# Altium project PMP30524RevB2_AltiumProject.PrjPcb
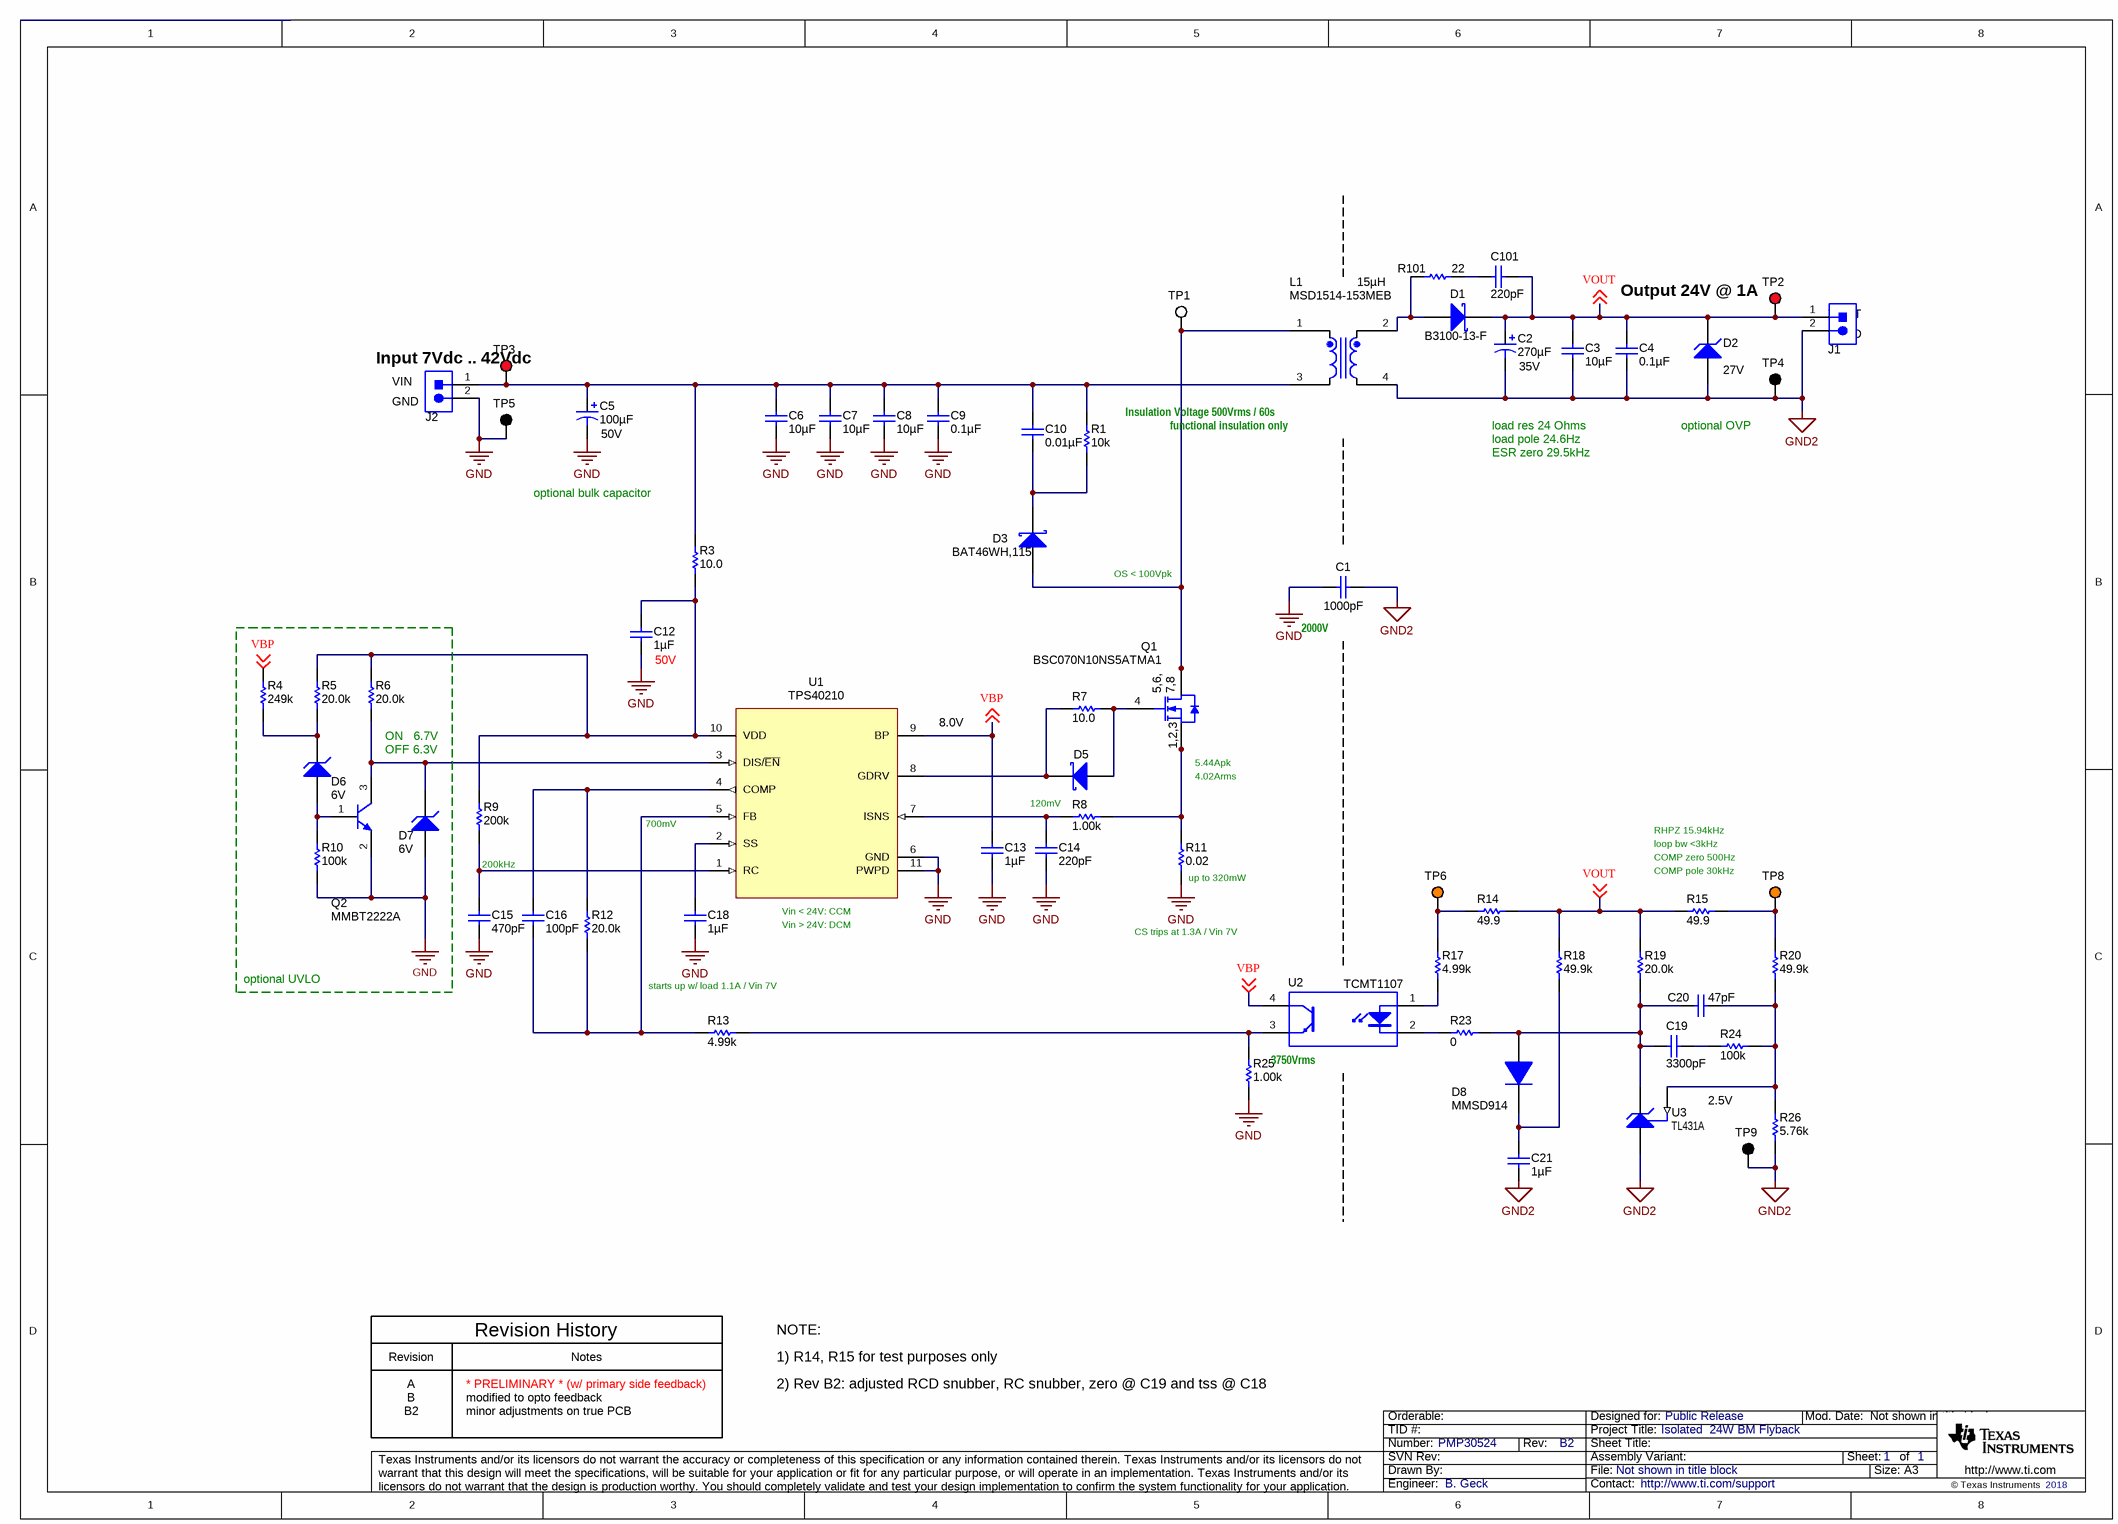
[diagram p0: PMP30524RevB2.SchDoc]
CopyrightYear: 2018; PCB_Layout: B. Geck; PCB_Rev: B; PRJ_Customer: Public Release; PRJ_Engineer: B. Geck; PRJ_Number: PMP30524; PRJ_Title: Isolated  24W BM Flyback; SCH_Rev: B2; TechSupport: http://www.ti.com/support
1 sheet, 66 parts. Net scope: global (net labels, ports and power ports of the same name join across sheets).

## Sheet PMP30524RevB2.SchDoc
size A3; Date: Not shown in title block; ApprovedBy: Not shown in title block; CheckedBy: Not shown in title block; Author: Not shown in title block; CompanyName: Not shown in title block; Engineer: Not shown in title block; Organization: Not shown in title block; Address1: Not shown in title block; Address2: Not shown in title block; Address3: Not shown in title block; Address4: Not shown in title block; DocumentNumber: 1; Revision: Use project parameter SCH_Rev; SheetNumber: 1; SheetTotal: 1; PageSetup: Record=PageOptions¦CenterHorizontal=True¦CenterVertical=True¦PrintScale=0.68¦XCorrection=1.00¦YCorrection=1.00¦PrintKind=0¦BorderSize=5000000¦LeftOffset=0¦BottomOffset=0¦Orientation=2¦PaperLength=1000¦PaperWidth=1000¦Scale=100¦PaperSource=15¦PrintQuality=600¦MediaType=1¦DitherType=10¦PrintScaleMode=1¦PaperKind=A4¦PaperIndex=9

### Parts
C1  ValueDisplayed: 1000pF  [1206_180]  (hidden comment: C1206C102KGRACAUTO)
C2  ValueDisplayed: 270µF  Value2: 35V  [SM_RADIAL_10BMM]  (hidden comment: EEHZC1V271P)
C3  ValueDisplayed: 10µF  [1210_270]  (hidden comment: GRM32ER71H106KA12L)
C4  ValueDisplayed: 0.1µF  [0603]  (hidden comment: GCM188R71H104KA57D)
C5  ValueDisplayed: 100µF  Value2: 50V  [SM_RADIAL_10BMM]  (hidden comment: EEHZC1H101P)
C6  ValueDisplayed: 10µF  [1210_270]  (hidden comment: GRM32ER71H106KA12L)
C7  ValueDisplayed: 10µF  [1210_270]  (hidden comment: GRM32ER71H106KA12L)
C8  ValueDisplayed: 10µF  [1210_270]  (hidden comment: GRM32ER71H106KA12L)
C9  ValueDisplayed: 0.1µF  [0603]  (hidden comment: GCM188R71H104KA57D)
C10  ValueDisplayed: 0.01µF  [0805_HV]  (hidden comment: GRM21BR72A103MA01L)
C12  ValueDisplayed: 1µF  Value2: 50V  [0603]  (hidden comment: UMK107AB7105KA-T)
C13  ValueDisplayed: 1µF  [0603]  (hidden comment: GRM188R71C105KA12D)
C14  ValueDisplayed: 220pF  [0603]  (hidden comment: GRM188R71H221KA01D)
C15  ValueDisplayed: 470pF  [0603]  (hidden comment: GRM1885C1H471JA01D)
C16  ValueDisplayed: 100pF  [0603]  (hidden comment: GRM1885C1H101JA01D)
C18  ValueDisplayed: 1µF  [0603]  (hidden comment: GRM188R71C105KA12D)
C19  ValueDisplayed: 3300pF  [0603]  (hidden comment: GRM188R71E332KA01D)
C20  ValueDisplayed: 47pF  [0603]  (hidden comment: GRM1885C1H470JA01D)
C21  ValueDisplayed: 1µF  [0603]  (hidden comment: GRM188R71C105KA12D)
C101  ValueDisplayed: 220pF  [0805_HV]  (hidden comment: GRM2165C2A221JA01D)
D1  B3100-13-F  [SMC]
D2  value 27V  [SOD-123]  (hidden comment: MMSZ5254B-7-F)
D3  BAT46WH,115  [SOD-123F]
D5  BAT54LP-7  [X1-DFN1006-2]  (value not drawn)
D6  value 6V  [SOD-323]  (hidden comment: MMSZ5233BS-7-F)
D7  value 6V  [SOD-323]  (hidden comment: MMSZ5233BS-7-F)
D8  MMSD914  [SOD-123]
J1  ED555/2DS  [TERM_BLK_ED555-2DS]  (value not drawn)
J2  ED555/2DS  [TERM_BLK_ED555-2DS]  (value not drawn)
L1  MSD1514-153MEB  ValueDisplayed: 15µH  [MSD1514]
Q1  BSC070N10NS5ATMA1  [PG-TDSON-8]
Q2  MMBT2222A  [SOT-23]
R1  ValueDisplayed: 10k  [1206]  (hidden comment: CRCW120610K0JNEA)
R3  ValueDisplayed: 10.0  [0603]  (hidden comment: CRCW060310R0FKEA)
R4  ValueDisplayed: 249k  [0603]  (hidden comment: CRCW0603249KFKEA)
R5  ValueDisplayed: 20.0k  [0603]  (hidden comment: CRCW060320K0FKEA)
R6  ValueDisplayed: 20.0k  [0603]  (hidden comment: CRCW060320K0FKEA)
R7  ValueDisplayed: 10.0  [0603]  (hidden comment: CRCW060310R0FKEA)
R8  ValueDisplayed: 1.00k  [0603]  (hidden comment: CRCW06031K00FKEA)
R9  ValueDisplayed: 200k  [0603]  (hidden comment: CRCW0603200KFKEA)
R10  value 100k  [0603]  (hidden comment: CRCW0603100KFKEA)
R11  ValueDisplayed: 0.02  [WSLP0805]  (hidden comment: WSLP0805R0200FEB)
R12  ValueDisplayed: 20.0k  [0603]  (hidden comment: CRCW060320K0FKEA)
R13  ValueDisplayed: 4.99k  [0603]  (hidden comment: CRCW06034K99FKEA)
R14  ValueDisplayed: 49.9  [0603]  (hidden comment: CRCW060349R9FKEA)
R15  ValueDisplayed: 49.9  [0603]  (hidden comment: CRCW060349R9FKEA)
R17  ValueDisplayed: 4.99k  [0603]  (hidden comment: CRCW06034K99FKEA)
R18  ValueDisplayed: 49.9k  [0603]  (hidden comment: CRCW060349K9FKEA)
R19  ValueDisplayed: 20.0k  [0603]  (hidden comment: CRCW060320K0FKEA)
R20  ValueDisplayed: 49.9k  [0603]  (hidden comment: CRCW060349K9FKEA)
R23  ValueDisplayed: 0  [0603]  (hidden comment: CRCW06030000Z0EA)
R24  ValueDisplayed: 100k  [0603]  (hidden comment: CRCW0603100KFKEA)
R25  ValueDisplayed: 1.00k  [0603]  (hidden comment: CRCW06031K00FKEA)
R26  ValueDisplayed: 5.76k  [0603]  (hidden comment: CRCW06035K76FKEA)
R101  ValueDisplayed: 22  [1206]  (hidden comment: CRCW120622R0JNEA)
TP1  5002  [Keystone5002]  (value not drawn)
TP2  5000  [Keystone5000]  (value not drawn)
TP3  5000  [Keystone5000]  (value not drawn)
TP4  5001  [Keystone5001]  (value not drawn)
TP5  5001  [Keystone5001]  (value not drawn)
TP6  5003  [Keystone5003]  (value not drawn)
TP8  5003  [Keystone5003]  (value not drawn)
TP9  5001  [Keystone5001]  (value not drawn)
U1  TPS40210  [DGQ0010D_N]
U2  TCMT1107  [SOP-4]
U3  TL431A  [DBZ0003A_N]

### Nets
GND: C1.2 C5.2(-) C6.2 C7.2 C8.2 C9.2 C12.2 C13.2 C14.2 C15.2 C18.2 D7.2(A) J2.2 Q2.2(E) R10.1 R11.1 R25.1 TP5.1 U1.6(GND) U1.11(PWPD)
GND2: C1.1 C2.2(-) C3.2 C4.2 C21.2 D2.2(A) J1.2 L1.4 R26.1 TP4.1 TP9.1 U3.3(ANODE)
VBP: C13.1 R4.2 U1.9(BP) U2.4(C) ; off-sheet VBP
VOUT: C2.1(+) C3.1 C4.1 C101.1 D1.1(K) D2.1(K) J1.1 R14.2 R15.1 R18.2 R19.2 TP2.1 ; off-sheet VOUT
NetC5_1: C5.1(+) C6.1 C7.1 C8.1 C9.1 C10.1 J2.1 L1.3 R1.2 R3.2 TP3.1
NetC10_2: C10.2 D3.1(K) R1.1
NetC12_1: C12.1 R3.1 R5.2 R6.2 R9.2 U1.10(VDD)
NetC14_1: C14.1 R8.1 U1.7(ISNS)
NetC15_1: C15.1 R9.1 U1.1(RC)
NetC16_1: C16.1 R12.2 U1.4(COMP)
NetC16_2: C16.2 R12.1 R13.2 U1.5(FB)
NetC18_1: C18.1 U1.2(SS)
NetC19_1: C19.1 R24.1
NetC19_2: C19.2 C20.1 D8.2(A) R19.1 R23.1 U3.1(CATHODE)
NetC20_2: C20.2 R20.1 R24.2 R26.2 U3.2(REF)
NetC21_1: C21.1 D8.1(K) R18.1
NetC101_2: C101.2 R101.2
NetD1_2: D1.2(A) L1.2 R101.1
NetD3_2: D3.2(A) L1.1 Q1.5(D) Q1.6(D) Q1.7(D) Q1.8(D) Q1.9(D) TP1.1
NetD5_1: D5.1(K) R7.2 U1.8(GDRV)
NetD5_2: D5.2(A) Q1.4(G) R7.1
NetD6_1: D6.1(K) R4.1 R5.1
NetD6_2: D6.2(A) Q2.1(B) R10.2
NetD7_1: D7.1(K) Q2.3(C) R6.1 U1.3(DIS/~{EN})
NetQ1_1: Q1.1(S) Q1.2(S) Q1.3(S) R8.2 R11.2
NetR13_1: R13.1 R25.2 U2.3(E)
NetR14_1: R14.1 R17.2 TP6.1
NetR15_2: R15.2 R20.2 TP8.1
NetR17_1: R17.1 U2.1(A)
NetR23_2: R23.2 U2.2(K)

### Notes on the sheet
- Output 24V @ 1A
- (near J1) VOUT
- (near J1) GND
- (near J2) VIN
- (near J2) GND
- Input 7Vdc .. 42Vdc
- (near L1) Insulation Voltage 500Vrms / 60s
- (near L1) functional insulation only
- load res 24 Ohms
- load pole 24.6Hz
- ESR zero 29.5kHz
- optional OVP
- optional bulk capacitor
- OS < 100Vpk
- (near C1) 2000V
- (near R6) ON   6.7V
- (near U1) 8.0V
- OFF 6.3V
- 120mV
- (near Q1) 5.44Apk
- 4.02Arms
- 200kHz
- 700mV
- (near R11) up to 320mW
- RHPZ 15.94kHz
- loop bw <3kHz
- COMP zero 500Hz
- COMP pole 30kHz
- (near U1) Vin < 24V: CCM
- (near U1) Vin > 24V: DCM
- CS trips at 1.3A / Vin 7V
- optional UVLO
- starts up w/ load 1.1A / Vin 7V
- (near U2) 3750Vrms
- 2.5V
- Revision History
- NOTE:
- Revision
- A
- B
- B2
- * PRELIMINARY * (w/ primary side feedback)
- modified to opto feedback
- minor adjustments on true PCB
- Notes
- 1) R14, R15 for test purposes only
- 2) Rev B2: adjusted RCD snubber, RC snubber, zero @ C19 and tss @ C18

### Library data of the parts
C1 = C1206C102KGRACAUTO: CAP, CERM, 1000 pF, 2000 V,+/- 10%, X7R, AEC-Q200 Grade 1, 1206; Manufacturer: Kemet; Polarized: N; CompType: Capacitor; Value: 1000pF; U/M: EA; Cap_F: 0.000000001; Tolerance_%: 10; VDC_V: 2000; Value2: 2000V; TaMin_C: -55; TaMax_C: 125; Cap_Case: 1206; SizeArea_mm2: 5.12; SizeAreaWB_mm2: 10.92; SizeX_mm: 3.2; SizeY_mm: 1.6; SizeZ_mm: 1.8; AEC Category: Q200; AEC Qualified: Y; AEC Grade: 1
C2 = EEHZC1V271P: CAP, Polymer Hybrid, 270 µF, 35 V,+/- 20%, 20 ohm, 10x10 SMD; Manufacturer: Panasonic; Polarized: Y; CompType: Capacitor; Value: 270uF; U/M: EA; Cap_F: 0.00027; Tolerance_%: 20; Value1: 20 ohm; VDC_V: 35; IRMS_A: 2; TaMin_C: -55; TaMax_C: 125; SizeAreaWB_mm2: 159.9; SizeArea_mm2: 113.3; SizeX_mm: 11; SizeY_mm: 10.3; SizeZ_mm: 10.2; AEC Category: Q200
C3 C6-C8 = GRM32ER71H106KA12L: CAP, CERM, 10 µF, 50 V,+/- 10%, X7R, 1210; Manufacturer: MuRata; Polarized: N; CompType: Capacitor; Value: 10uF; U/M: EA; Cap_F: 0.00001; Tolerance_%: 10; Value1: Unknown; VDC_V: 50; Value2: 50V; TaMin_C: -55; TaMax_C: 125; Cap_Case: 1210; SizeArea_mm2: 8; SizeAreaWB_mm2: 14.7; SizeX_mm: 3.2; SizeY_mm: 2.5; SizeZ_mm: 2.7; AEC Category: Q200; Green_Lifecycle: Active; Green_REACh: Passed
C4 C9 = GCM188R71H104KA57D: CAP, CERM, 0.1 µF, 50 V, +/- 10%, X7R, 0603; Manufacturer: MuRata; Polarized: N; CompType: Capacitor; Value: 0.1uF; U/M: EA; Cap_F: 0.0000001; Tolerance_%: 10; ESR_ohm: 0.02; Value1: 0.02 ohm; VDC_V: 50; Value2: 50V; IRMS_A: 1.84; TaMin_C: -55; TaMax_C: 125; AEC Category: Q200
C5 = EEHZC1H101P: CAP, Polymer Hybrid, 100 µF, 50 V,+/- 20%, 28 ohm, 10x10 SMD; Manufacturer: Panasonic; Polarized: Y; CompType: Capacitor; Value: 100uF; U/M: EA; Cap_F: 0.0001; Tolerance_%: 20; Value1: 28 ohm; VDC_V: 50; ESR_ohm: 28; IRMS_A: 1.6; TaMin_C: -55; TaMax_C: 125; SizeAreaWB_mm2: 159.9; SizeArea_mm2: 113.3; SizeX_mm: 11; SizeY_mm: 10.3; SizeZ_mm: 10.2; AEC Category: Q200; Green_Lifecycle: Active; Green_REACh: Passed
C10 = GRM21BR72A103MA01L: CAP, CERM, 0.01 µF, 100 V, +/- 20%, X7R, 0805; Manufacturer: MuRata; Polarized: N; CompType: Capacitor; Value: 0.01uF; U/M: EA; Cap_F: 0.00000001; Tolerance_%: 20; Value1: Unknown; VDC_V: 100; Value2: 100V; TaMin_C: -55; TaMax_C: 125; Cap_Case: 0805; SizeArea_mm2: 2.5; SizeAreaWB_mm2: 6.75; SizeX_mm: 2; SizeY_mm: 1.25; SizeZ_mm: 1.45; AEC Category: Q200
C12 = UMK107AB7105KA-T: CAP, CERM, 1 µF, 50 V,+/- 10%, X7R, 0603; Manufacturer: Taiyo Yuden; Polarized: N; CompType: Capacitor; Value: 1uF; U/M: EA; Cap_F: 0.000001; Tolerance_%: 10; VDC_V: 50; TaMin_C: -55; TaMax_C: 125; SizeArea_mm2: 1.28; SizeAreaWB_mm2: 4.68; SizeX_mm: 1.6; SizeY_mm: 0.8; SizeZ_mm: 1; AEC Category: Q200; Green_Lifecycle: Active; Green_REACh: Passed
C13 C21 = GRM188R71C105KA12D: CAP, CERM, 1 µF, 16 V, +/- 10%, X7R, 0603; Manufacturer: MuRata; Polarized: N; CompType: Capacitor; Value: 1uF; U/M: EA; Cap_F: 0.000001; Tolerance_%: 10; ESR_ohm: 0.011; Value1: 0.011 ohm; VDC_V: 16; Value2: 16V; TaMin_C: -55; TaMax_C: 125; AEC Category: Q200
C14 = GRM188R71H221KA01D: CAP, CERM, 220 pF, 50 V,+/- 10%, X7R, 0603; Manufacturer: MuRata; Polarized: N; CompType: Capacitor; Value: 220pF; U/M: EA; Cap_F: 0.00000000022; Tolerance_%: 10; Value1: Unknown; VDC_V: 50; Value2: 50V; TaMin_C: -55; TaMax_C: 125; SizeArea_mm2: 1.28; SizeAreaWB_mm2: 4.68; SizeX_mm: 1.6; SizeY_mm: 0.8; SizeZ_mm: 1; AEC Category: Q200; Green_Lifecycle: Active; Green_REACh: Passed
C15 = GRM1885C1H471JA01D: CAP, CERM, 470 pF, 50 V, +/- 5%, C0G/NP0, 0603; Manufacturer: MuRata; Polarized: N; CompType: Capacitor; Value: 470pF; U/M: EA; Cap_F: 0.00000000047; Tolerance_%: 5; Value1: Unknown; VDC_V: 50; Value2: 50V; TaMin_C: -55; TaMax_C: 125; SizeArea_mm2: 1.28; SizeAreaWB_mm2: 4.68; SizeX_mm: 1.6; SizeY_mm: 0.8; SizeZ_mm: 1; AEC Category: Q200
C16 = GRM1885C1H101JA01D: CAP, CERM, 100 pF, 50 V,+/- 5%, C0G/NP0, 0603; Manufacturer: MuRata; Polarized: N; CompType: Capacitor; Value: 100pF; U/M: EA; Cap_F: 0.0000000001; Tolerance_%: 5; VDC_V: 50; Value2: 50V; TaMin_C: -55; TaMax_C: 125; SizeArea_mm2: 1.28; SizeAreaWB_mm2: 4.68; SizeX_mm: 1.6; SizeY_mm: 0.8; SizeZ_mm: 1; AEC Category: Q200; Green_Lifecycle: Active; Green_REACh: Passed
C18 = GRM188R71C105KA12D: CAP, CERM, 1 µF, 16 V,+/- 10%, X7R, 0603; Manufacturer: MuRata; Polarized: N; CompType: Capacitor; Value: 1uF; U/M: EA; Cap_F: 0.000001; Tolerance_%: 10; ESR_ohm: 0.011; Value1: 0.011 ohm; VDC_V: 16; Value2: 16V; TaMin_C: -55; TaMax_C: 125; SizeArea_mm2: 1.28; SizeAreaWB_mm2: 4.68; SizeX_mm: 1.6; SizeY_mm: 0.8; SizeZ_mm: 1; AEC Category: Q200; Green_Lifecycle: Active; Green_REACh: Passed
C19 = GRM188R71E332KA01D: CAP, CERM, 3300 pF, 25 V,+/- 10%, X7R, 0603; Manufacturer: MuRata; Polarized: N; CompType: Capacitor; Value: 3300pF; U/M: EA; Cap_F: 0.0000000033; Tolerance_%: 10; VDC_V: 25; Value2: 25V; TaMin_C: -55; TaMax_C: 125; SizeArea_mm2: 1.28; SizeAreaWB_mm2: 4.68; SizeX_mm: 1.6; SizeY_mm: 0.8; SizeZ_mm: 1; AEC Category: Q200; Green_Lifecycle: Active; Green_REACh: Passed
C20 = GRM1885C1H470JA01D: CAP, CERM, 47 pF, 50 V,+/- 5%, C0G/NP0, 0603; Manufacturer: MuRata; Polarized: N; CompType: Capacitor; Value: 47pF; U/M: EA; Cap_F: 0.000000000047; Tolerance_%: 5; VDC_V: 50; Value2: 50V; TaMin_C: -55; TaMax_C: 125; SizeArea_mm2: 1.28; SizeAreaWB_mm2: 4.68; SizeX_mm: 1.6; SizeY_mm: 0.8; SizeZ_mm: 1; AEC Category: Q200; Green_Lifecycle: Active; Green_REACh: Passed
C101 = GRM2165C2A221JA01D: CAP, CERM, 220 pF, 100 V,+/- 5%, C0G/NP0, 0805; Manufacturer: MuRata; Polarized: N; CompType: Capacitor; Value: 220pF; U/M: EA; Cap_F: 0.00000000022; Tolerance_%: 5; VDC_V: 100; Value2: 100V; TaMin_C: -55; TaMax_C: 125; Cap_Case: 0805; SizeArea_mm2: 2.5; SizeAreaWB_mm2: 6.75; SizeX_mm: 2; SizeY_mm: 1.25; SizeZ_mm: 1.45; AEC Category: Q200
D1 = B3100-13-F: Diode, Schottky, 100 V, 3 A, SMC; Manufacturer: Diodes Inc.; U/M: EA; Vf_V: 0.79; Value: 100V; Value1: 3A; Value2: 0.79V; Io_A: 3; Vr_V: 100; TJmax_C: 125; RJC_CperW: 10; SizeAreaWB_mm2: 83.2686; SizeArea_mm2: 50.5686; SizeX_mm: 8.13; SizeY_mm: 6.22; SizeZ_mm: 2.6; AEC Category: Q101; Green_Lifecycle: Active; Green_REACh: Passed
D2 = MMSZ5254B-7-F: Diode, Zener, 27 V, 500 mW, SOD-123; Manufacturer: Diodes Inc.; SymbolCreator: a0412235; U/M: EA; Power_W: 0.5; Vz_V: 27; Value1: 0.5W; RJA_CperW: 350; SizeAreaWB_mm2: 13.095; SizeArea_mm2: 6.545; SizeX_mm: 3.85; SizeY_mm: 1.7; SizeZ_mm: 1.35; AEC Category: Q101
D3 = BAT46WH,115: Diode, Schottky, 100 V, 0.25 A, SOD-123F; Manufacturer: Nexperia; U/M: EA; Vf_V: 0.85; Value: 100V; Value1: 0.25A; Value2: 0.85V; Io_A: 0.25; Vr_V: 100; TJmax_C: 150; SizeAreaWB_mm2: 11.7; SizeArea_mm2: 5.6; SizeX_mm: 3.5; SizeY_mm: 1.6; SizeZ_mm: 1.1; AEC Category: Q101; Green_Lifecycle: Not Set; Green_REACh: Incomplete
D5 = BAT54LP-7: Diode, Schottky, 30 V, 0.2 A, 1.00x0.50x0.60mm; Manufacturer: Diodes Inc.; U/M: EA; Vf_V: 1; Value: 30V; Value1: 0.2A; Value2: 1V; Io_A: 0.2; Vr_V: 30; SizeAreaWB_mm2: 3.2; SizeArea_mm2: 0.6; SizeZ_mm: 0.53; AEC Category: Q101; Green_Lifecycle: Not Set; Green_REACh: Incomplete
D6 D7 = MMSZ5233BS-7-F: Diode, Zener, 6 V, 200 mW, SOD-323; Manufacturer: Diodes Inc.; SymbolCreator: a0412235; U/M: EA; Power_W: 0.2; Vz_V: 6; Value1: 0.2W; RJA_CperW: 350; SizeAreaWB_mm2: 8.695; SizeArea_mm2: 3.645; SizeX_mm: 2.7; SizeY_mm: 1.35; SizeZ_mm: 1; AEC Category: Q101
D8 = MMSD914T1G: Diode, Switching, 100 V, 0.2 A, SOD-123; Manufacturer: ON Semiconductor; U/M: EA; Value: 100V; Value1: 0.2A; Io_A: 0.2; Vr_V: 100; TJmax_C: 150; SizeAreaWB_mm2: 13.095; SizeArea_mm2: 6.545; SizeX_mm: 3.85; SizeY_mm: 1.7; SizeZ_mm: 1.35; AEC Category: Q101
J1 J2 = ED555/2DS: Terminal Block, 6A, 3.5mm Pitch, 2-Pos, TH; Manufacturer: On-Shore Technology; SymbolCreator: a0412235; CompType: Connector; U/M: EA
L1 = MSD1514-103MEB: Coupled inductor, 15 µH, 3.4Arms, 0.028 ohm, SMD; Manufacturer: Coilcraft; SymbolCreator: a0412235; SizeAreaWB_mm2: 289; SizeArea_mm2: 225; SizeX_mm: 15; SizeZ_mm: 14.2; Value: 15uH; Ind_H: 15.0E-6; DCR_ohm: 0.028; AEC Category: Q200; AEC Qualified: N
Q1 = BSC070N10NS5ATMA1: MOSFET, N-CH, 100 V, 80 A, PG-TDSON-8; Manufacturer: Infineon Technologies; Alternate Manufacturer: None; U/M: EA; ChType: N; Value: 100V; VdsMax_V: 100; Value1: ? ohm; Value2: 30 nC; QgTyp_nC: 30; Vgs_V: 20; IdsMax_A: 80; SizeAreaWB_mm2: 55.131; SizeArea_mm2: 29.351; SizeX_mm: 5.99; SizeY_mm: 4.9; SizeZ_mm: 1.12; AEC Category: Q101; Green_Lifecycle: Not Set; Green_REACh: Incomplete
Q2 = MMBT2222A, Fairchild Semiconductor: Transistor, NPN, 40V, 0.15A, SOT-23; CompType: BJT; PNP: 0; NPN: 1; Vceo_V: 40; Vcesat1_V: 0.3; Value: 0.3V; IcRated_A: 0.15; HfeMax: 300; TaMin_C: -55; TaMax_C: 150; U/M: EA
R1 = CRCW120610K0JNEA: RES, 10 k, 5%, 0.25 W, 1206; Manufacturer: Vishay-Dale; CompType: Resistor; Value: 10k; Res_ohm: 10000; Value_Code: 10k0; Tolerance_%: 5; Power_W: 0.25; Value2: 0.25W; VDC_V: 200; TempCo: 200 ppm/C; SizeArea_mm2: 5.12; SizeX_mm: 3.2; SizeY_mm: 1.6; SizeZ_mm: 1.35; EIA_Code: E24; U/M: EA; AEC Category: Q200
R3 R7 = CRCW060310R0FKEA: RES, 10.0, 1%, 0.1 W, 0603; Manufacturer: Vishay-Dale; CompType: Resistor; Value: 10.0; Res_ohm: 10; Value_Code: 10R0; Tolerance_%: 1; Power_W: 0.1; Value2: 0.1W; VDC_V: 75; TempCo: 100 ppm/C; SizeArea_mm2: 1.28; SizeX_mm: 1.6; SizeY_mm: 0.8; EIA_Code: E96; U/M: EA; AEC Category: Q200
R4 = CRCW0603249KFKEA: RES, 249 k, 1%, 0.1 W, 0603; Manufacturer: Vishay-Dale; CompType: Resistor; Value: 249k; Res_ohm: 249000; Tolerance_%: 1; Power_W: 0.1; Value2: 0.1W; VDC_V: 75; TempCo: 100 ppm/C; SizeArea_mm2: 1.28; SizeX_mm: 1.6; SizeY_mm: 0.8; EIA_Code: E96; U/M: EA; AEC Category: Q200; Green_Lifecycle: Active; Green_REACh: Passed
R5 R6 = CRCW060320K0FKEA: RES, 20.0 k, 1%, 0.1 W, 0603; Manufacturer: Vishay-Dale; CompType: Resistor; Value: 20.0k; Res_ohm: 20000; Value_Code: 20k0; Tolerance_%: 1; Power_W: 0.1; Value2: 0.1W; VDC_V: 75; TempCo: 100 ppm/C; SizeArea_mm2: 1.28; SizeX_mm: 1.6; SizeY_mm: 0.8; EIA_Code: E96; U/M: EA; AEC Category: Q200; Green_Lifecycle: Active; Green_REACh: Passed
R8 = CRCW06031K00FKEA: RES, 1.00 k, 1%, 0.1 W, 0603; Manufacturer: Vishay-Dale; CompType: Resistor; Value: 1.00k; Res_ohm: 1000; Value_Code: 1k00; Tolerance_%: 1; Power_W: 0.1; Value2: 0.1W; VDC_V: 75; TempCo: 100 ppm/C; EIA_Code: E96; U/M: EA
R9 = CRCW0603200KFKEA: RES, 200 k, 1%, 0.1 W, 0603; Manufacturer: Vishay-Dale; CompType: Resistor; Value: 200k; Res_ohm: 200000; Tolerance_%: 1; Power_W: 0.1; Value2: 0.1W; VDC_V: 75; TempCo: 100 ppm/C; SizeArea_mm2: 1.28; SizeX_mm: 1.6; SizeY_mm: 0.8; EIA_Code: E96; U/M: EA; AEC Category: Q200; Green_Lifecycle: Active; Green_REACh: Passed
R10 = CRCW0603100KFKEA: RES, 100k ohm, 1%, 0.1W, 0603; Manufacturer: Vishay-Dale; CompType: Resistor; Res_ohm: 100000; Tolerance_%: 1; Power_W: 0.1; VDC_V: 75; TempCo: 100 ppm/C; EIA_Code: E96; U/M: EA
R11 = WSLP0805R0200FEB: RES, 0.02, 1%, 0.5 W, 0805; Manufacturer: Vishay-Dale; CompType: Resistor; Value: 0.02; Value_Code: R020; Tolerance_%: 1; Power_W: 0.5; Value2: 0.5W; TempCo: 75 ppm/C; SizeArea_mm2: 2.5781; SizeX_mm: 2.03; SizeY_mm: 1.27; SizeZ_mm: 0.635; EIA_Code: E96; U/M: EA; AEC Category: Q200; AEC Qualified: N
R12 R19 = CRCW060320K0FKEA: RES, 20.0 k, 1%, 0.1 W, 0603; Manufacturer: Vishay-Dale; CompType: Resistor; Value: 20.0k; Res_ohm: 20000; Value_Code: 20k0; Tolerance_%: 1; Power_W: 0.1; Value2: 0.1W; VDC_V: 75; TempCo: 100 ppm/C; SizeArea_mm2: 1.28; SizeX_mm: 1.6; SizeY_mm: 0.8; EIA_Code: E96; U/M: EA; AEC Category: Q200
R13 R17 = CRCW06034K99FKEA: RES, 4.99 k, 1%, 0.1 W, 0603; Manufacturer: Vishay-Dale; CompType: Resistor; Value: 4.99k; Res_ohm: 4990; Value_Code: 4k99; Tolerance_%: 1; Power_W: 0.1; Value2: 0.1W; VDC_V: 75; TempCo: 100 ppm/C; SizeArea_mm2: 1.28; SizeX_mm: 1.6; SizeY_mm: 0.8; EIA_Code: E96; U/M: EA; AEC Category: Q200; Green_Lifecycle: Active; Green_REACh: Passed
R14 R15 = CRCW060349R9FKEA: RES, 49.9, 1%, 0.1 W, 0603; Manufacturer: Vishay-Dale; CompType: Resistor; Value: 49.9; Value_Code: 49R9; Tolerance_%: 1; Power_W: 0.1; Value2: 0.1W; VDC_V: 75; TempCo: 100 ppm/C; SizeArea_mm2: 1.28; SizeX_mm: 1.6; SizeY_mm: 0.8; EIA_Code: E96; U/M: EA; AEC Category: Q200
R18 R20 = CRCW060349K9FKEA: RES, 49.9 k, 1%, 0.1 W, 0603; Manufacturer: Vishay-Dale; CompType: Resistor; Value: 49.9k; Res_ohm: 49900; Value_Code: 49k9; Tolerance_%: 1; Power_W: 0.1; Value2: 0.1W; VDC_V: 75; TempCo: 100 ppm/C; SizeArea_mm2: 1.28; SizeX_mm: 1.6; SizeY_mm: 0.8; EIA_Code: E96; U/M: EA; AEC Category: Q200; Green_Lifecycle: Active; Green_REACh: Passed
R23 = CRCW06030000Z0EA: RES, 0, 5%, 0.1 W, 0603; Manufacturer: Vishay-Dale; CompType: Resistor; Value: 0; Value_Code: 0000; Tolerance_%: 5; Power_W: 0.1; Value2: 0.1W; VDC_V: 75; TempCo: 200 ppm/C; SizeArea_mm2: 1.28; SizeX_mm: 1.6; SizeY_mm: 0.8; SizeZ_mm: 1; EIA_Code: E24; U/M: EA; AEC Category: Q200
R24 = CRCW0603100KFKEA: RES, 100 k, 1%, 0.1 W, 0603; Manufacturer: Vishay-Dale; CompType: Resistor; Value: 100k; Res_ohm: 100000; Tolerance_%: 1; Power_W: 0.1; Value2: 0.1W; VDC_V: 75; TempCo: 100 ppm/C; SizeArea_mm2: 1.28; SizeX_mm: 1.6; SizeY_mm: 0.8; EIA_Code: E96; U/M: EA; AEC Category: Q200
R25 = CRCW06031K00FKEA: RES, 1.00 k, 1%, 0.1 W, 0603; Manufacturer: Vishay-Dale; CompType: Resistor; Value: 1.00k; Res_ohm: 1000; Value_Code: 1k00; Tolerance_%: 1; Power_W: 0.1; Value2: 0.1W; VDC_V: 75; TempCo: 100 ppm/C; SizeArea_mm2: 1.28; SizeX_mm: 1.6; SizeY_mm: 0.8; EIA_Code: E96; U/M: EA; AEC Category: Q200
R26 = CRCW06035K76FKEA: RES, 5.76 k, 1%, 0.1 W, 0603; Manufacturer: Vishay-Dale; CompType: Resistor; Value: 5.76k; Res_ohm: 5760; Value_Code: 5k76; Tolerance_%: 1; Power_W: 0.1; Value2: 0.1W; VDC_V: 75; TempCo: 100 ppm/C; SizeArea_mm2: 1.28; SizeX_mm: 1.6; SizeY_mm: 0.8; EIA_Code: E96; U/M: EA; AEC Category: Q200; Green_Lifecycle: Active; Green_REACh: Passed
R101 = CRCW120622R0JNEA: RES, 22, 5%, 0.25 W, 1206; Manufacturer: Vishay-Dale; CompType: Resistor; Value: 22; Value_Code: 22R0; Tolerance_%: 5; Power_W: 0.25; Value2: 0.25W; VDC_V: 200; TempCo: 200 ppm/C; SizeArea_mm2: 5.12; SizeX_mm: 3.2; SizeY_mm: 1.6; SizeZ_mm: 1.35; EIA_Code: E24; U/M: EA; AEC Category: Q200
TP1 = 5002: Test Point, Miniature, White, TH; Manufacturer: Keystone; CompType: Test Point Loop; ContactFinish: Silver
TP2 TP3 = 5000: Test Point, Miniature, Red, TH; Manufacturer: Keystone; CompType: Test Point Loop; U/M: EA
TP4 TP5 TP9 = 5001: Test Point, Miniature, Black, TH; Manufacturer: Keystone; CompType: Test Point Loop; U/M: EA
TP6 TP8 = 5003: Test Point, Miniature, Orange, TH; Manufacturer: Keystone; CompType: Test Point Loop; ContactFinish: Silver
U1 = TPS40210QDGQRQ1: 4.5-V TO 52-V INPUT CURRENT MODE BOOST CONTROLLER, DGQ0010D; PartNumber: TPS40210DGQ; Manufacturer: Texas Instruments; SymbolCreator: a0412235; CompType: IC; U/M: EA
U2 = TCMT1107: Optocoupler, 3.75 kV, 80-160% CTR, SMT; Manufacturer: Vishay-Semiconductor; CTR (Min): 80%; CTR (Max): 160%; Voltage_Isolation_Vrms: 3750V; SizeAreaWB_mm2: 43.65; SizeArea_mm2: 19.95; SizeX_mm: 7; SizeY_mm: 2.85; SizeZ_mm: 2.3
U3 = TL431AIDBZR: Adjustable Precision Shunt Regulator, 34 ppm / degC, 100 mA, -40 to 85 degC, 3-pin SOT-23 (DBZ), Green (RoHS & no Sb/Br); Manufacturer: Texas Instruments; Alternate PartNumber: Equivalent; Initial Accuracy @ 25/deg C(%): 1; Iout/Iz(Max)(mA): 100; Min Iz for Regulation(uA): 600; Rating: Catalog; SubFamily: Shunt Voltage Reference; Temp Coeff(Max)(ppm/ degree C): 92; Temp Coeff(Typ)(ppm/ degree C): 34; VO Adj(Max)(V): 36; VO Adj(Min)(V): 2.495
